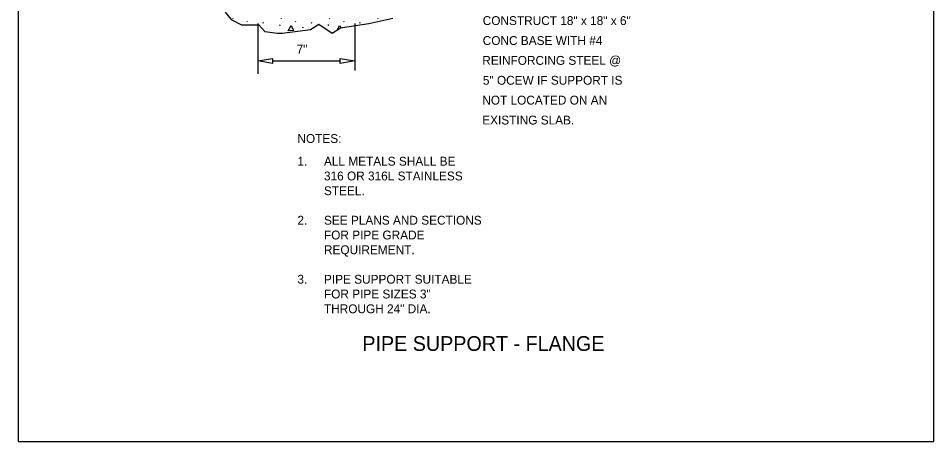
# Model space of a CAD drawing. Extents: x 2147138 to 2147698, y 2147153 to 2147515.
# Drawn here: x 2147427.3 to 2147551.5, y 2147351.3 to 2147408.7 of the extents above; entities that cross this region are included whole.
import ezdxf

# ---------------------------------------------------------------- set-up
doc = ezdxf.new("R2010")
doc.units = 0
for name, color, linetype in [('1', 7, 'Continuous'), ('G-ANNO-TEXT-LW10', 7, 'Continuous'), ('G-ANNO-TITL', 7, 'Continuous'), ('G-DETL-PATT', 7, 'Continuous'), ('PATTERN_CLASS', 7, 'Continuous')]:
    doc.layers.add(name, color=color, linetype=linetype)

msp = doc.modelspace()

# ---------------------------------------------------------------- linework, layer by layer
at = {"layer": '1'}
for p, q in [((2147456.34, 2147408.65), (2147456.39, 2147408.56)), ((2147462.9, 2147408.65), (2147462.96, 2147408.56)), ((2147469.46, 2147408.65), (2147469.52, 2147408.56)), ((2147476.02, 2147408.65), (2147476.08, 2147408.56)), ((2147458.3, 2147408.27), (2147458.36, 2147408.19)), ((2147460.52, 2147407.99), (2147460.57, 2147408.12)), ((2147462.79, 2147407.69), (2147462.85, 2147407.82)), ((2147463.93, 2147406.96), (2147464.32, 2147407.7)), ((2147464.32, 2147407.7), (2147464.63, 2147407.02)), ((2147464.86, 2147408.27), (2147464.92, 2147408.19)), ((2147465.9, 2147407.35), (2147465.96, 2147407.48)), ((2147467.08, 2147407.99), (2147467.14, 2147408.12)), ((2147469.35, 2147407.69), (2147469.41, 2147407.82)), ((2147470.54, 2147407.05), (2147470.89, 2147407.7)), ((2147470.89, 2147407.7), (2147471.04, 2147407.36)), ((2147471.42, 2147408.27), (2147471.48, 2147408.19)), ((2147473.64, 2147407.99), (2147473.7, 2147408.12)), ((2147464.63, 2147407.02), (2147463.94, 2147406.96))]:
    msp.add_line(p, q, dxfattribs=at)
at = {"layer": 'G-ANNO-TEXT-LW10'}
for p, q in [((2147459.79, 2147407.97), (2147459.79, 2147401.59)), ((2147472.98, 2147407.97), (2147472.98, 2147401.59)), ((2147459.79, 2147406.7), (2147459.79, 2147401.11)), ((2147461.79, 2147402.87), (2147470.98, 2147402.87))]:
    msp.add_line(p, q, dxfattribs=at)
for points in [[(2147461.79, 2147402.54), (2147459.79, 2147402.87), (2147461.79, 2147403.2)], [(2147470.98, 2147403.2), (2147472.98, 2147402.87), (2147470.98, 2147402.54)]]:
    msp.add_lwpolyline(points, close=True, dxfattribs=at)
at = {"layer": 'G-DETL-PATT'}
for p, q in [((2147455.36, 2147409.49), (2147456.18, 2147408.47)), ((2147456.18, 2147408.47), (2147457.6, 2147407.76)), ((2147474.88, 2147407.96), (2147478.13, 2147408.67)), ((2147457.6, 2147407.76), (2147459.94, 2147407.76)), ((2147459.94, 2147407.76), (2147460.75, 2147406.85)), ((2147466.95, 2147407.15), (2147468.07, 2147407.86)), ((2147468.07, 2147407.86), (2147469.9, 2147406.64)), ((2147469.9, 2147406.64), (2147471.02, 2147407.35)), ((2147471.02, 2147407.35), (2147473.05, 2147407.66)), ((2147473.05, 2147407.66), (2147474.88, 2147407.96)), ((2147460.75, 2147406.85), (2147462.48, 2147406.64)), ((2147462.48, 2147406.64), (2147463.09, 2147406.64)), ((2147463.09, 2147406.64), (2147466.95, 2147407.15))]:
    msp.add_line(p, q, dxfattribs=at)
at = {"layer": 'PATTERN_CLASS'}
for p, q in [((2147427.3, 2147503.54), (2147427.3, 2147351.27)), ((2147551.49, 2147351.27), (2147551.49, 2147503.54)), ((2147427.3, 2147351.27), (2147551.49, 2147351.27)), ((2147427.3, 2147351.27), (2147427.3, 2147351.27))]:
    msp.add_line(p, q, dxfattribs=at)

# ---------------------------------------------------------------- texts
at = {"layer": 'G-ANNO-TEXT-LW10'}
for s, p in [('CONSTRUCT 18" x 18" x 6"', (2147490.31, 2147407.74)), ('CONC BASE WITH #4', (2147490.31, 2147405.04)), ('7"', (2147465.06, 2147403.87)), ('REINFORCING STEEL @', (2147490.25, 2147402.35)), ('5" OCEW IF SUPPORT IS', (2147490.33, 2147399.65)), ('NOT LOCATED ON AN', (2147490.25, 2147396.96)), ('EXISTING SLAB.', (2147490.24, 2147394.26)), ('NOTES:', (2147465.17, 2147391.76)), ('1.', (2147465.17, 2147388.68)), ('ALL METALS SHALL BE ', (2147468.77, 2147388.68)), ('316 OR 316L STAINLESS ', (2147468.77, 2147386.68)), ('STEEL.', (2147468.77, 2147384.68)), ('2.', (2147465.17, 2147380.68)), ('SEE PLANS AND SECTIONS ', (2147468.77, 2147380.68)), ('FOR PIPE GRADE ', (2147468.77, 2147378.68)), ('REQUIREMENT.', (2147468.77, 2147376.68)), ('3.', (2147465.17, 2147372.68)), ('PIPE SUPPORT SUITABLE ', (2147468.77, 2147372.68)), ('FOR PIPE SIZES 3" ', (2147468.77, 2147370.68)), ('THROUGH 24" DIA.', (2147468.77, 2147368.68))]:
    msp.add_text(s, height=1.2, dxfattribs=at).set_placement(p)
at = {"layer": 'G-ANNO-TITL'}
msp.add_text('PIPE SUPPORT - FLANGE', height=2, dxfattribs=at).set_placement((2147473.98, 2147363.57))

doc.saveas('drawing.dxf')
